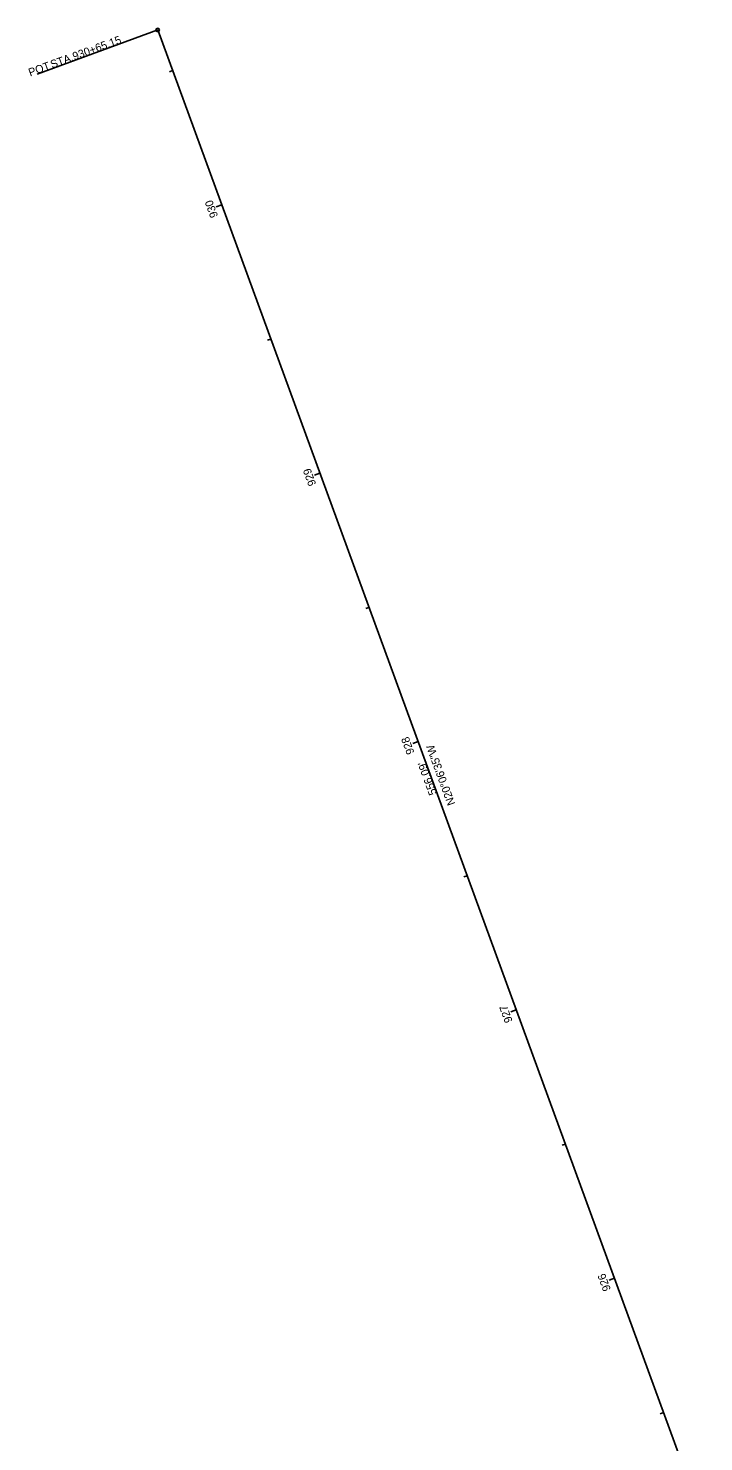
# Model space of a CAD drawing. Extents: x 145633 to 146120, y 414528 to 417535.
# Drawn here: x 145632.8 to 145869.3, y 417040 to 417534.6 of the extents above; entities that cross this region are included whole.
import ezdxf

# ---------------------------------------------------------------- set-up
doc = ezdxf.new("R2010")
doc.units = 0
for name, color, linetype in [('GE_X_Alignment', 7, 'Continuous'), ('GE_X_Alignment_100_Bearings', 7, 'Continuous'), ('GE_X_Alignment_100_Cardinal_Points', 7, 'Continuous'), ('GE_X_Alignment_100_Distances', 7, 'Continuous'), ('GE_X_Alignment_100_Stations', 7, 'Continuous'), ('SC_Scratch3', 7, 'Continuous')]:
    doc.layers.add(name, color=color, linetype=linetype)

msp = doc.modelspace()

# ---------------------------------------------------------------- linework, layer by layer
at = {"layer": 'GE_X_Alignment'}
msp.add_line((145869.32, 417011.82), (145678.13, 417534.01), dxfattribs=at)
at = {"layer": 'GE_X_Alignment_100_Cardinal_Points'}
msp.add_line((145678.13, 417534.01), (145635.87, 417518.54), dxfattribs=at)
msp.add_circle((145678.13, 417534.01), 0.6, dxfattribs=at)
at = {"layer": 'GE_X_Alignment_100_Stations'}
for p, q in [((145683.34, 417519.78), (145682.21, 417519.37)), ((145700.53, 417472.83), (145698.65, 417472.14)), ((145717.72, 417425.88), (145716.59, 417425.46)), ((145734.91, 417378.92), (145733.03, 417378.24)), ((145752.1, 417331.97), (145750.98, 417331.56)), ((145769.29, 417285.02), (145767.42, 417284.33)), ((145786.48, 417238.07), (145785.36, 417237.66)), ((145803.68, 417191.12), (145801.8, 417190.43)), ((145820.87, 417144.17), (145819.74, 417143.75)), ((145838.06, 417097.21), (145836.18, 417096.53)), ((145855.25, 417050.26), (145854.12, 417049.85))]:
    msp.add_line(p, q, dxfattribs=at)
at = {"layer": 'SC_Scratch3'}
msp.add_line((145678.13, 417534.01), (145869.32, 417011.82), dxfattribs=at)

# ---------------------------------------------------------------- texts
at = {"layer": 'GE_X_Alignment_100_Bearings'}
msp.add_text('N20°06\'35"W', height=2.8, rotation=110.1097, dxfattribs=at).set_placement((145782.37, 417263.27))
at = {"layer": 'GE_X_Alignment_100_Cardinal_Points'}
for s, p in [('930+65.15', (145648.92, 417523.35)), ('POT', (145633.47, 417517.7)), (' STA. ', (145640.17, 417520.15))]:
    msp.add_text(s, height=2.8, rotation=20.1097, dxfattribs=at).set_placement(p)
at = {"layer": 'GE_X_Alignment_100_Distances'}
msp.add_text("556.09'", height=2.8, rotation=110.1097, dxfattribs=at).set_placement((145775.91, 417266.86))
at = {"layer": 'GE_X_Alignment_100_Stations'}
for s, p in [('930', (145699.31, 417468.9)), ('929', (145733.67, 417375.04)), ('928', (145768.06, 417281.11)), ('927', (145802.44, 417187.21)), ('926', (145836.83, 417093.3))]:
    msp.add_text(s, height=2.8, rotation=110.1097, dxfattribs=at).set_placement(p)

doc.saveas('drawing.dxf')
